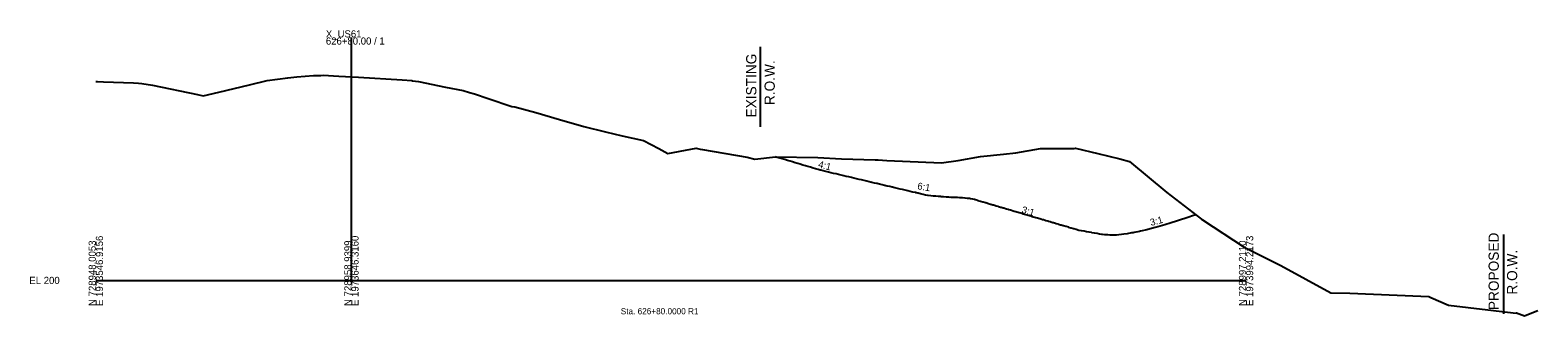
# Model space of a CAD drawing. Extents: x -26 to 630, y -39 to 9098.
# Drawn here: x -26 to 564, y 6986 to 7098 of the extents above; entities that cross this region are included whole.
import ezdxf

# ---------------------------------------------------------------- set-up
doc = ezdxf.new("R2010")
doc.units = 0
for name, color, linetype in [('CONST_DCH', 7, 'Continuous'), ('Default', 7, 'Continuous'), ('Draft_XS_Grid', 7, 'Continuous'), ('Draft_XS_Text', 7, 'Continuous'), ('DTM_X_GROUND', 7, 'Continuous'), ('X_DTM_CONTOURS_MAJOR', 7, 'Continuous'), ('XS_CELL', 7, 'Continuous'), ('XS_P_GROUND', 7, 'Continuous'), ('XS_P_ROW', 7, 'Continuous'), ('XS_P_TX_FS_BS', 7, 'Continuous'), ('XS_X_ROW', 7, 'Continuous')]:
    doc.layers.add(name, color=color, linetype=linetype)

msp = doc.modelspace()

# ---------------------------------------------------------------- linework, layer by layer
at = {"layer": 'DTM_X_GROUND'}
msp.add_lwpolyline([(0, 7077.75), (0.63, 7077.75), (2.94, 7077.68), (14.76, 7077.3), (16.69, 7077.12), (17.98, 7077), (22.14, 7076.28), (39.81, 7072.71), (42.03, 7072.23), (48.07, 7073.65), (60.07, 7076.49), (67, 7078.14), (75.09, 7079.24), (78.63, 7079.54), (85.11, 7080.09), (88, 7080.18), (88.93, 7080.21), (95.06, 7079.87), (102.72, 7079.46), (119.83, 7078.36), (123.57, 7078.12), (123.84, 7078.08), (126.18, 7077.76), (136.77, 7075.62), (143.72, 7074.2), (146.17, 7073.49), (148.17, 7072.93), (153.45, 7071.07), (162.8, 7068.02), (163.99, 7067.81), (172.18, 7065.64), (181.44, 7062.85), (190.87, 7060.16), (199.46, 7058.12), (205.97, 7056.53), (214.31, 7054.66), (220.3, 7051.62), (223.85, 7049.61), (232.76, 7051.26), (234.83, 7051.64), (236.46, 7051.33), (237.41, 7051.15), (254.81, 7048.16), (257.85, 7047.45), (265.87, 7048.37), (282.44, 7048.07), (291.75, 7047.51), (304.91, 7047.16), (306.13, 7047.16), (309.41, 7046.85), (330.91, 7046.03), (337.39, 7046.83), (346.15, 7048.41), (355.1, 7049.3), (359.98, 7049.88), (369.55, 7051.59), (382.73, 7051.51), (383.27, 7051.65), (392, 7049.68), (400.56, 7047.54), (404.39, 7046.44), (419.02, 7034.32), (432.56, 7023.99), (432.83, 7023.81), (433.02, 7023.68), (449.31, 7012.99), (463.63, 7005.87), (483.12, 6995.09), (490.67, 6995.04), (518.34, 6993.88), (521.46, 6993.77), (522.24, 6993.27), (529.19, 6990.33), (554.51, 6987.34), (555.73, 6987.22), (555.8, 6987.27), (558.98, 6986.15), (558.99, 6986.15), (558.99, 6986.15), (558.99, 6986.15), (559.15, 6986.22), (564.16, 6988.2)], dxfattribs=at)
at = {"layer": 'XS_CELL'}
for p, q in [((100, 7000), (100, 7095)), ((0, 7000), (100, 7000)), ((100, 7000), (450, 7000))]:
    msp.add_line(p, q, dxfattribs=at)
at = {"layer": 'XS_P_GROUND'}
for points in [[(334.06, 7032.47), (333.63, 7032.5), (332.63, 7032.58), (331.63, 7032.66), (330.63, 7032.75), (329.63, 7032.83), (328.63, 7032.91), (327.63, 7032.99), (326.63, 7033.07), (325.62, 7033.15), (325.45, 7033.17), (324.62, 7033.36), (323.62, 7033.6), (322.62, 7033.83), (321.62, 7034.07), (320.62, 7034.31), (319.62, 7034.54), (318.62, 7034.78), (317.62, 7035.02), (316.62, 7035.25), (315.62, 7035.49), (314.62, 7035.72), (313.62, 7035.96), (312.62, 7036.2), (311.61, 7036.43), (310.61, 7036.67), (309.61, 7036.9), (308.61, 7037.14), (307.61, 7037.38), (306.61, 7037.61), (305.61, 7037.85), (304.61, 7038.08), (303.61, 7038.32), (302.61, 7038.56), (301.61, 7038.79), (300.61, 7039.03), (299.61, 7039.27), (298.61, 7039.5), (297.6, 7039.74), (296.6, 7039.97), (295.6, 7040.21), (294.6, 7040.45), (293.6, 7040.68), (292.6, 7040.92), (291.6, 7041.15), (290.6, 7041.39), (289.6, 7041.63), (288.6, 7041.86), (287.6, 7042.1), (286.6, 7042.34), (285.6, 7042.57), (284.6, 7042.81), (283.59, 7043.04), (283.42, 7043.08), (282.59, 7043.33), (281.59, 7043.63), (280.59, 7043.93), (279.59, 7044.23), (278.59, 7044.52), (277.59, 7044.82), (276.59, 7045.12), (275.59, 7045.42), (274.59, 7045.72), (273.59, 7046.01), (272.59, 7046.31), (271.59, 7046.61), (270.59, 7046.91), (269.58, 7047.21), (268.58, 7047.5), (267.58, 7047.8), (266.58, 7048.1), (265.75, 7048.35)], [(343.71, 7031.58), (343.1, 7031.73), (343.09, 7031.73), (342.2, 7031.94), (342.19, 7031.95), (342.08, 7031.96), (342.08, 7031.96), (341.09, 7032.04), (341.07, 7032.05), (340.09, 7032.13), (340.06, 7032.14), (339.09, 7032.22), (339.04, 7032.23), (338.09, 7032.31), (338.03, 7032.32), (337.09, 7032.4), (337.02, 7032.41), (336.73, 7032.44), (336.71, 7032.44), (335.58, 7032.44), (334.46, 7032.45), (333.69, 7032.5), (333.63, 7032.5), (332.71, 7032.58), (332.63, 7032.58), (331.7, 7032.66), (331.63, 7032.66), (330.7, 7032.74), (330.63, 7032.75), (329.7, 7032.82), (329.63, 7032.83), (328.69, 7032.9), (328.63, 7032.91), (327.69, 7032.98), (327.63, 7032.99), (326.69, 7033.07), (326.63, 7033.07), (325.68, 7033.15), (325.62, 7033.15), (325.46, 7033.17), (325.45, 7033.17), (324.67, 7033.35), (324.62, 7033.36), (323.68, 7033.59), (323.62, 7033.6), (322.67, 7033.82), (322.62, 7033.83), (321.67, 7034.06), (321.62, 7034.07), (320.67, 7034.3), (320.62, 7034.31), (319.66, 7034.53), (319.62, 7034.54), (318.66, 7034.77), (318.62, 7034.78), (317.66, 7035.01), (317.62, 7035.02), (316.65, 7035.24), (316.62, 7035.25), (315.65, 7035.48), (315.62, 7035.49), (314.65, 7035.72), (314.62, 7035.72), (313.64, 7035.95), (313.62, 7035.96), (312.64, 7036.19), (312.62, 7036.2), (311.64, 7036.43), (311.61, 7036.43), (310.63, 7036.66), (310.61, 7036.67), (309.63, 7036.9), (309.61, 7036.9), (308.63, 7037.14), (308.61, 7037.14), (307.62, 7037.37), (307.61, 7037.38), (306.62, 7037.61), (306.61, 7037.61), (305.62, 7037.85), (305.61, 7037.85), (304.61, 7038.08), (304.61, 7038.08), (303.61, 7038.32), (303.61, 7038.32), (303.4, 7038.37)], [(384.52, 7019.57), (383.55, 7019.85), (383.53, 7019.86), (382.57, 7020.15), (382.52, 7020.16), (381.58, 7020.44), (381.51, 7020.46), (380.59, 7020.73), (380.5, 7020.75), (379.61, 7021.02), (379.48, 7021.05), (378.62, 7021.31), (378.47, 7021.35), (377.63, 7021.6), (377.46, 7021.65), (376.65, 7021.89), (376.45, 7021.94), (375.66, 7022.18), (375.44, 7022.24), (374.67, 7022.47), (374.43, 7022.54), (373.69, 7022.76), (373.42, 7022.84), (372.7, 7023.05), (372.41, 7023.13), (371.71, 7023.34), (371.4, 7023.43), (370.73, 7023.63), (370.39, 7023.73), (369.74, 7023.92), (369.37, 7024.03), (368.75, 7024.21), (368.36, 7024.32), (367.77, 7024.5), (367.35, 7024.62), (366.78, 7024.79), (366.34, 7024.92), (365.79, 7025.08), (365.33, 7025.22), (364.81, 7025.37), (364.32, 7025.51), (363.82, 7025.66), (363.31, 7025.81), (362.83, 7025.95), (362.3, 7026.11), (361.85, 7026.24), (361.29, 7026.41), (360.86, 7026.53), (360.28, 7026.7), (359.87, 7026.82), (359.26, 7027), (358.89, 7027.11), (358.25, 7027.3), (357.9, 7027.4), (357.24, 7027.6), (356.92, 7027.69), (356.23, 7027.89), (355.93, 7027.98), (355.22, 7028.19), (354.94, 7028.27), (354.21, 7028.49), (353.96, 7028.56), (353.2, 7028.79), (352.97, 7028.85), (352.19, 7029.08), (351.98, 7029.14), (351.18, 7029.38), (351, 7029.43), (350.17, 7029.68), (350.01, 7029.72), (349.15, 7029.98), (349.02, 7030.01), (348.14, 7030.27), (348.04, 7030.3), (347.13, 7030.57), (347.05, 7030.59), (346.12, 7030.87), (346.06, 7030.88), (345.11, 7031.17), (345.08, 7031.18), (344.1, 7031.46), (344.09, 7031.47), (343.71, 7031.58)], [(430.4, 7025.68), (428.67, 7025.08), (428.02, 7024.86), (422.84, 7023.16), (420.74, 7022.52), (418.22, 7021.74), (415.54, 7020.98), (414.4, 7020.66), (411.53, 7019.92), (411.15, 7019.82), (408.73, 7019.26), (408.32, 7019.16), (406.21, 7018.74), (405.78, 7018.65), (405.21, 7018.56), (403.47, 7018.26), (402.21, 7018.09), (401.32, 7017.96), (400.25, 7017.85), (399.29, 7017.75), (397.61, 7017.73), (396.67, 7017.71), (395.94, 7017.77), (395.66, 7017.79), (394.91, 7017.85), (394.65, 7017.87), (393.9, 7017.93), (393.68, 7017.95), (393.65, 7017.96), (393.64, 7017.96), (392.83, 7018.1), (392.63, 7018.14), (391.8, 7018.28), (391.62, 7018.32), (390.76, 7018.47), (390.6, 7018.5), (389.72, 7018.65), (389.59, 7018.67), (388.69, 7018.83), (388.58, 7018.85), (387.65, 7019.02), (387.57, 7019.03), (386.61, 7019.2), (386.56, 7019.21), (385.58, 7019.38), (385.55, 7019.39), (384.54, 7019.57), (384.54, 7019.57), (384.52, 7019.57)]]:
    msp.add_lwpolyline(points, dxfattribs=at)
at = {"layer": 'XS_P_ROW'}
msp.add_line((550.73, 7017.96), (550.73, 6986.95), dxfattribs=at)
at = {"layer": 'XS_X_ROW'}
msp.add_line((260, 7060), (260, 7091.36), dxfattribs=at)

# ---------------------------------------------------------------- texts
at = {"layer": 'CONST_DCH'}
for p in [(384.52, 7019.57), (408.73, 7019.26)]:
    msp.add_text('X', height=0.001, dxfattribs=at).set_placement(p)
at = {"layer": 'Default'}
for height, p in [(0.12, (302.24, 7047.17)), (0.001, (303.4, 7038.37)), (0.12, (427.72, 7027.6)), (0.001, (384.52, 7019.57))]:
    msp.add_text('X', height=height, dxfattribs=at).set_placement(p)
at = {"layer": 'Draft_XS_Grid'}
msp.add_text('-', height=0.0001, dxfattribs=at).set_placement((0, 7000))
at = {"layer": 'Draft_XS_Text'}
msp.add_text('Sta. 626+80.0000 R1', height=2.4, dxfattribs=at).set_placement((205.37, 6986.75))
at = {"layer": 'X_DTM_CONTOURS_MAJOR'}
msp.add_text('X', height=0.12, dxfattribs=at).set_placement((250.12, 7058.58))
at = {"layer": 'XS_CELL'}
for s, p in [('X_US61', (90, 7095)), ('626+80.00 / 1', (90, 7092.2)), ('EL 200', (-26, 6998.6))]:
    msp.add_text(s, height=2.8, dxfattribs=at).set_placement(p)
for s, p in [('N 728948.0053', (0, 6990)), ('E 1973546.9156', (2.8, 6990)), ('N 728958.9399', (100, 6990)), ('E 1973646.3160', (102.8, 6990)), ('N 728997.2110', (450, 6990)), ('E 1973994.2173', (452.8, 6990))]:
    msp.add_text(s, height=2.8, rotation=90, dxfattribs=at).set_placement(p)
at = {"layer": 'XS_P_ROW'}
for s, p in [('EXISTING', (258.43, 7063.7)), ('R.O.W.', (265.63, 7068.55)), ('PROPOSED', (548.89, 6988.37)), ('R.O.W.', (556.09, 6994.44))]:
    msp.add_text(s, height=4, rotation=90, dxfattribs=at).set_placement(p)
at = {"layer": 'XS_P_TX_FS_BS'}
for s, rotation, p in [('4:1', 345.15596, (282.43, 7044.24)), ('6:1', 350.43426, (321.28, 7035.66)), ('3:1', 343.60514, (362, 7026.51)), ('3:1', 14.82543, (412.85, 7021.28))]:
    msp.add_text(s, height=2.7, rotation=rotation, dxfattribs=at).set_placement(p)

doc.saveas('drawing.dxf')
